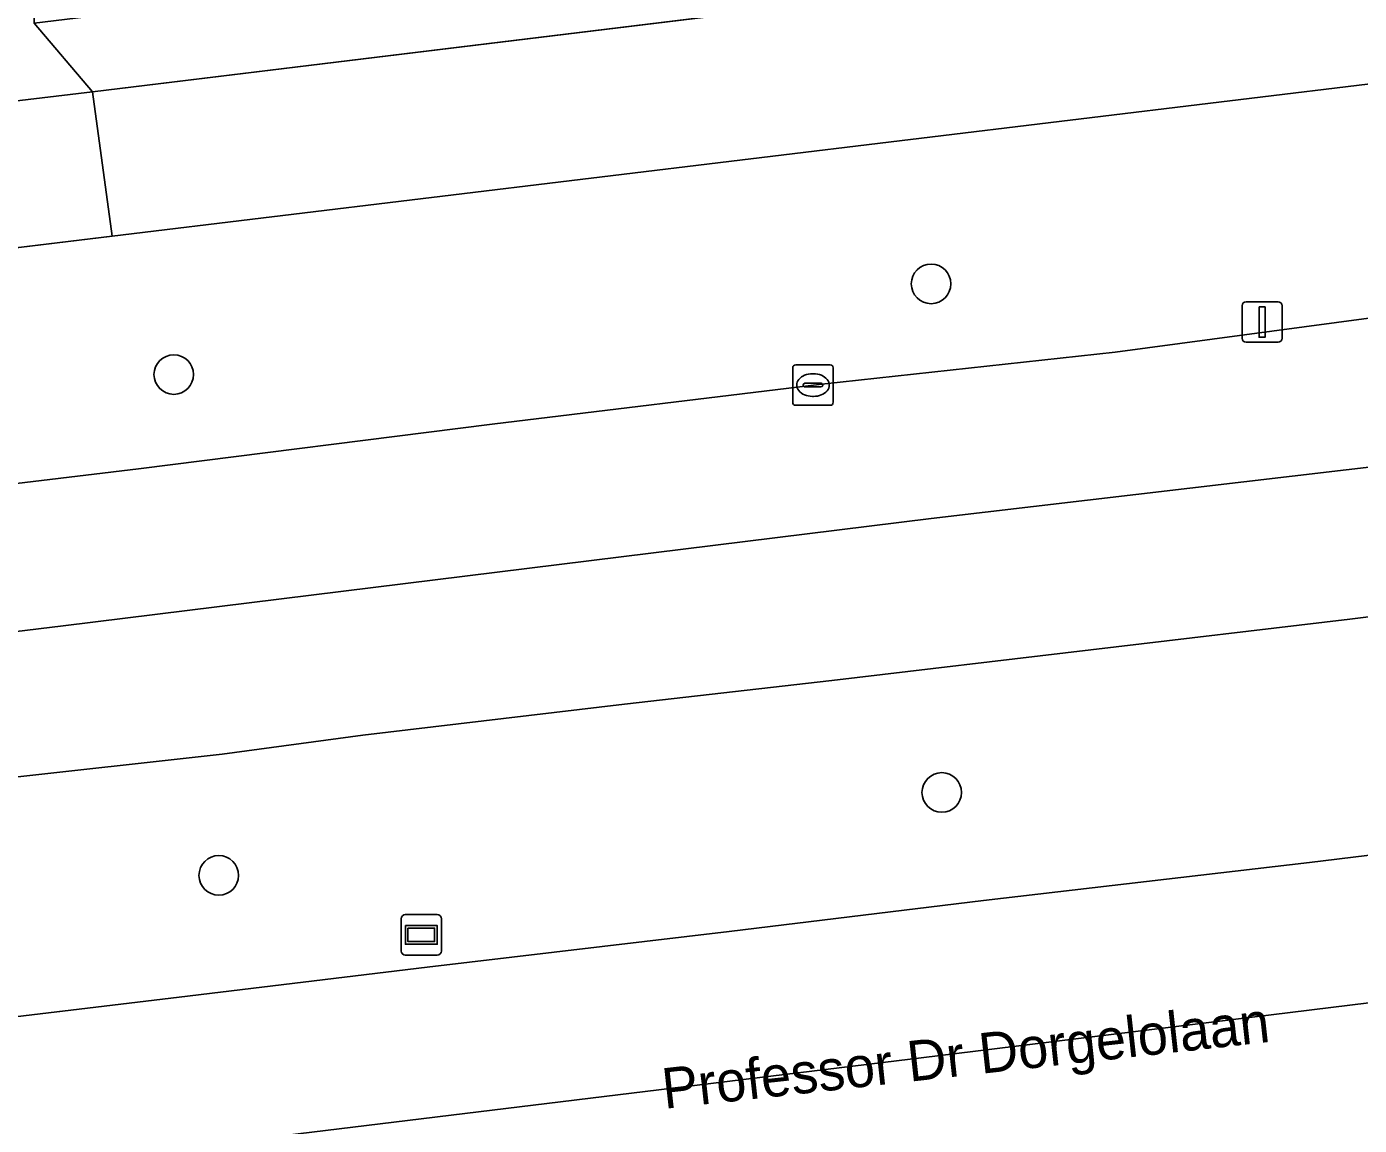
# Model space of a CAD drawing. Extents: x 161477 to 163040, y 383680 to 384871.
# Drawn here: x 161894.85 to 161927.77, y 384024.24 to 384051.39 of the extents above; entities that cross this region are included whole.
import ezdxf

# ---------------------------------------------------------------- set-up
doc = ezdxf.new("R2010")
doc.units = 0
for name, color, linetype in [('IMGEO_Berm_groen', 7, 'Continuous'), ('IMGEO_Boom', 7, 'Continuous'), ('IMGEO_Fietspad_gesloten', 7, 'Continuous'), ('IMGEO_Fietspad_open', 7, 'Continuous'), ('IMGEO_Kolk', 7, 'Continuous'), ('IMGEO_Lichtmast', 7, 'Continuous'), ('IMGEO_Openbare_ruimte_label', 7, 'Continuous'), ('IMGEO_Rijbaan_lokaal_gesloten', 7, 'Continuous'), ('IMGEO_Verklikker', 7, 'Continuous')]:
    doc.layers.add(name, color=color, linetype=linetype)

msp = doc.modelspace()

# ---------------------------------------------------------------- linework, layer by layer
at = {"layer": 'IMGEO_Berm_groen'}
for points in [[(162179.927, 384080.597), (162164.799, 384078.716), (162037.295, 384063.34), (162003.42, 384059.174), (162000, 384058.753), (161967.373, 384054.741), (161896.962, 384046.212), (161847.953, 384040.275), (161822.49, 384037.235), (161793.606, 384033.742), (161792.05, 384033.368), (161791.016, 384033.255), (161789.879, 384033.126), (161782.08, 384032.349)], [(162186.915, 384068.26), (162005.779, 384046.356), (162000, 384045.657), (161987.218, 384044.084), (161979.791, 384043.121), (161973.119, 384042.354), (161968.425, 384041.721), (161962.69, 384041.055), (161956.209, 384040.252), (161949.03, 384039.374), (161942.719, 384038.556), (161935.229, 384037.691), (161927.541, 384036.751), (161914.738, 384035.23), (161909.622, 384034.647), (161903.15, 384033.885), (161899.681, 384033.408), (161894.025, 384032.784), (161888.791, 384032.099), (161882.389, 384031.339), (161877.612, 384030.793), (161870.482, 384029.937), (161863.792, 384029.049), (161858.477, 384028.412)], [(161854.166, 384022.062), (161862.148, 384023.025), (161868.493, 384023.755), (161875.103, 384024.611), (161881.096, 384025.303), (161887.995, 384026.183), (161892.7, 384026.697), (161898.618, 384027.408), (161904.739, 384028.152), (161912.208, 384029.026), (161918.49, 384029.795), (161926.538, 384030.732), (161932.884, 384031.511), (161941.167, 384032.594), (161947.767, 384033.359), (161955.645, 384034.342), (161962.463, 384035.163), (161969.768, 384036.032), (161974.918, 384036.586), (161982.858, 384037.61), (161991.596, 384038.663), (162000, 384039.742), (162006.847, 384040.554), (162097.498, 384051.298)], [(161857.408, 384035.62), (161864.1, 384036.367), (161869.714, 384037.111), (161875.008, 384037.786), (161883.145, 384038.766), (161890.894, 384039.656), (161897.615, 384040.464), (161906.349, 384041.566), (161914.495, 384042.556), (161921.737, 384043.345), (161928.805, 384044.291), (161936.424, 384045.158), (161943.431, 384046.103), (161949.126, 384046.758), (161956.536, 384047.591), (161962.567, 384048.414), (161970.007, 384049.256), (161977.435, 384050.21)]]:
    msp.add_lwpolyline(points, dxfattribs=at)
msp.add_lwpolyline([(162036.674, 384066.924), (162037.582, 384067.034), (162038.924, 384068.822), (162038.896, 384068.971), (162005.124, 384064.883), (161960.6, 384059.493), (161945.247, 384057.634), (161922.11, 384054.757), (161918.446, 384054.301), (161918.491, 384054.006), (161916.62, 384053.79), (161916.531, 384054.083), (161895.034, 384051.475), (161896.476, 384049.775), (161967.056, 384058.389), (162000, 384062.428), (162002.758, 384062.766)], close=True, dxfattribs=at)
at = {"layer": 'IMGEO_Boom'}
for centre in [(161917.192, 384045.031), (161898.482, 384042.79), (161917.456, 384032.466), (161899.594, 384030.417)]:
    msp.add_circle(centre, 0.489, dxfattribs=at)
at = {"layer": 'IMGEO_Fietspad_gesloten'}
for points in [[(162179.402, 384084.189), (162164.301, 384082.326), (162042.321, 384067.606), (162040.757, 384067.417), (162037.582, 384067.034), (162036.674, 384066.924), (162002.758, 384062.766), (162000, 384062.428), (161967.056, 384058.389), (161896.476, 384049.775), (161896.962, 384046.212), (161967.373, 384054.741), (162000, 384058.753), (162003.42, 384059.174), (162037.295, 384063.34), (162164.799, 384078.716)], [(161847.953, 384040.275), (161896.962, 384046.212), (161896.476, 384049.775), (161890.591, 384049.076), (161847.567, 384043.886)]]:
    msp.add_lwpolyline(points, dxfattribs=at)
at = {"layer": 'IMGEO_Fietspad_open'}
msp.add_lwpolyline([(161897.004, 384079.075), (161891.942, 384079.096), (161891.888, 384056.155), (161891.776, 384056.158), (161891.77, 384053.173), (161891.768, 384052.371), (161891.774, 384051.718), (161891.78, 384051.119), (161891.806, 384050.865), (161891.59, 384050.536), (161890.591, 384049.076), (161896.476, 384049.775), (161895.034, 384051.475), (161895.041, 384052.157), (161895.037, 384052.736), (161895.031, 384053.614), (161895.016, 384055.979), (161895.02, 384056.148), (161894.977, 384067.394)], dxfattribs=at)
at = {"layer": 'IMGEO_Kolk'}
for p, q in [((161913.774, 384042.105), (161913.774, 384042.957)), ((161913.849, 384043.031), (161914.701, 384043.031)), ((161914.262, 384042.811), (161914.287, 384042.811)), ((161914.775, 384042.957), (161914.775, 384042.105)), ((161914.033, 384042.525), (161914.033, 384042.537)), ((161914.471, 384042.488), (161914.073, 384042.488)), ((161914.076, 384042.574), (161914.474, 384042.574)), ((161914.517, 384042.537), (161914.517, 384042.525)), ((161914.285, 384042.251), (161914.26, 384042.251)), ((161914.701, 384042.031), (161913.849, 384042.031))]:
    msp.add_line(p, q, dxfattribs=at)
for points in [[(161913.774, 384042.105), (161913.774, 384042.957)], [(161913.849, 384043.031), (161914.701, 384043.031)], [(161914.775, 384042.957), (161914.775, 384042.105)], [(161914.701, 384042.031), (161913.849, 384042.031)]]:
    msp.add_lwpolyline(points, dxfattribs=at)
for centre, radius, start, end in [((161913.851, 384042.955), 0.0765, 91.552, 178.448), ((161913.851, 384042.955), 0.0765, 91.552, 178.448), ((161914.699, 384042.955), 0.0765, 1.552, 88.448), ((161914.699, 384042.955), 0.0765, 1.552, 88.448), ((161914.073, 384042.534), 0.0403, 85.8775, 175.7526), ((161914.07, 384042.524), 0.0366, 178.938, 274.7102), ((161914.474, 384042.531), 0.043, 264.8664, 352.4533), ((161914.478, 384042.536), 0.0386, 1.7309, 96.639), ((161913.851, 384042.107), 0.0765, 181.552, 268.448), ((161913.851, 384042.107), 0.0765, 181.552, 268.448), ((161914.699, 384042.107), 0.0765, 271.552, 358.448), ((161914.699, 384042.107), 0.0765, 271.552, 358.448)]:
    msp.add_arc(centre, radius, start, end, dxfattribs=at)
for centre, major_axis, ratio, start_param, end_param in [((161914.261, 384042.531), (-0.387, 0.002), 0.722429, 4.712389, 7.853982), ((161914.286, 384042.531), (-0.39, 0.002), 0.717154, 1.570796, 4.712389)]:
    msp.add_ellipse(centre, major_axis=major_axis, ratio=ratio, start_param=start_param, end_param=end_param, dxfattribs=at)
at = {"layer": 'IMGEO_Lichtmast'}
for p, q in [((161924.875, 384043.688), (161924.875, 384044.488)), ((161924.875, 384044.488), (161924.875, 384043.688)), ((161924.975, 384044.588), (161925.765, 384044.588)), ((161925.765, 384044.588), (161924.975, 384044.588)), ((161925.865, 384044.488), (161925.865, 384043.688)), ((161925.865, 384043.688), (161925.865, 384044.488)), ((161925.765, 384043.588), (161924.975, 384043.588)), ((161924.975, 384043.588), (161925.765, 384043.588))]:
    msp.add_line(p, q, dxfattribs=at)
msp.add_lwpolyline([(161925.295, 384044.463), (161925.445, 384044.463), (161925.445, 384043.713), (161925.295, 384043.713), (161925.295, 384044.463)], dxfattribs=at)
for centre, start, end in [((161924.975, 384044.488), 90, 180), ((161924.975, 384044.488), 90, 180), ((161925.765, 384044.488), 0, 90), ((161925.765, 384044.488), 360, 90), ((161924.975, 384043.688), 180, 270), ((161924.975, 384043.688), 180, 270), ((161925.765, 384043.688), 270, 0), ((161925.765, 384043.688), 270, 0)]:
    msp.add_arc(centre, 0.1, start, end, dxfattribs=at)
at = {"layer": 'IMGEO_Rijbaan_lokaal_gesloten'}
for points in [[(161858.477, 384028.412), (161863.792, 384029.049), (161870.482, 384029.937), (161877.612, 384030.793), (161882.389, 384031.339), (161888.791, 384032.099), (161894.025, 384032.784), (161899.681, 384033.408), (161903.15, 384033.885), (161909.622, 384034.647), (161914.738, 384035.23), (161927.541, 384036.751), (161935.229, 384037.691), (161942.719, 384038.556), (161949.03, 384039.374), (161956.209, 384040.252), (161962.69, 384041.055), (161968.425, 384041.721), (161973.119, 384042.354), (161979.791, 384043.121), (161987.218, 384044.084), (162000, 384045.657), (162005.779, 384046.356), (162186.915, 384068.26)], [(162061.99, 384060.529), (162004.465, 384053.494), (162000, 384052.948), (161996.3, 384052.485), (161989.699, 384051.67), (161982.251, 384050.756), (161977.435, 384050.21), (161970.007, 384049.256), (161962.567, 384048.414), (161956.536, 384047.591), (161949.126, 384046.758), (161943.431, 384046.103), (161936.424, 384045.158), (161928.805, 384044.291), (161921.737, 384043.345), (161914.495, 384042.556), (161906.349, 384041.566), (161897.615, 384040.464), (161890.894, 384039.656), (161883.145, 384038.766), (161875.008, 384037.786), (161869.714, 384037.111), (161864.1, 384036.367), (161857.408, 384035.62)], [(161705.264, 384017.609), (161695.591, 384016.774), (161695.172, 384016.745), (161694.752, 384016.717), (161694.365, 384016.691), (161694.855, 384012.926), (161696.893, 384013.027), (161706.74, 384013.577), (161721.837, 384015.377), (161753.08, 384019.028), (161795.621, 384024.429), (161827.864, 384028.429), (161871.905, 384033.68), (161895.749, 384036.581), (161917.195, 384039.231), (161945.288, 384042.532), (161960.735, 384044.482), (161993.828, 384048.483), (162005.138, 384049.833), (162024.421, 384052.135)], [(162024.421, 384052.135), (162005.138, 384049.833), (161993.828, 384048.483), (161960.735, 384044.482), (161945.288, 384042.532), (161917.195, 384039.231), (161895.749, 384036.581), (161871.905, 384033.68), (161827.864, 384028.429)], [(162097.498, 384051.298), (162006.847, 384040.554), (162000, 384039.742), (161991.596, 384038.663), (161982.858, 384037.61), (161974.918, 384036.586), (161969.768, 384036.032), (161962.463, 384035.163), (161955.645, 384034.342), (161947.767, 384033.359), (161941.167, 384032.594), (161932.884, 384031.511), (161926.538, 384030.732), (161918.49, 384029.795), (161912.208, 384029.026), (161904.739, 384028.152), (161898.618, 384027.408), (161892.7, 384026.697), (161887.995, 384026.183), (161881.096, 384025.303), (161875.103, 384024.611), (161868.493, 384023.755), (161862.148, 384023.025), (161854.166, 384022.062)], [(162102.422, 384048.613), (162008.923, 384037.209), (162007.495, 384037.033), (161917.35, 384025.954), (161825.477, 384014.75)], [(161825.477, 384014.75), (161917.35, 384025.954), (162007.495, 384037.033), (162008.923, 384037.209), (162102.422, 384048.613)]]:
    msp.add_lwpolyline(points, dxfattribs=at)
at = {"layer": 'IMGEO_Verklikker'}
for p, q in [((161904.103, 384028.546), (161904.103, 384029.346)), ((161904.103, 384029.346), (161904.103, 384028.546)), ((161904.203, 384029.446), (161904.993, 384029.446)), ((161904.993, 384029.446), (161904.203, 384029.446)), ((161905.093, 384029.346), (161905.093, 384028.546)), ((161905.093, 384028.546), (161905.093, 384029.346)), ((161904.993, 384028.446), (161904.203, 384028.446)), ((161904.203, 384028.446), (161904.993, 384028.446))]:
    msp.add_line(p, q, dxfattribs=at)
for points in [[(161904.204, 384029.178), (161904.992, 384029.178), (161904.992, 384028.714), (161904.204, 384028.714), (161904.204, 384029.178)], [(161904.269, 384029.113), (161904.269, 384028.779), (161904.927, 384028.779), (161904.927, 384029.113), (161904.269, 384029.113)]]:
    msp.add_lwpolyline(points, dxfattribs=at)
for centre, start, end in [((161904.203, 384029.346), 90, 180), ((161904.203, 384029.346), 90, 180), ((161904.993, 384029.346), 0, 90), ((161904.993, 384029.346), 360, 90), ((161904.203, 384028.546), 180, 270), ((161904.203, 384028.546), 180, 270), ((161904.993, 384028.546), 270, 0), ((161904.993, 384028.546), 270, 0)]:
    msp.add_arc(centre, 0.1, start, end, dxfattribs=at)

# ---------------------------------------------------------------- texts
at = {"layer": 'IMGEO_Openbare_ruimte_label'}
msp.add_text('Professor Dr Dorgelolaan', height=1, rotation=6.3149, dxfattribs=at).set_placement((161910.602, 384024.647))

doc.saveas('drawing.dxf')
